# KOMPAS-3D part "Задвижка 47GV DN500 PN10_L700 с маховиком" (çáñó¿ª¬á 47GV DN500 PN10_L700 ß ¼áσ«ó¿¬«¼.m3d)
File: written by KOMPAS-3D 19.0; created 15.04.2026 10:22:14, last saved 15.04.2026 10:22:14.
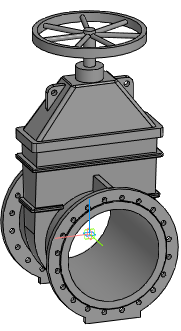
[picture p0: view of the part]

Document properties: Автор: Евгений; Полное имя файла: Z:\3.Личные\kachalov\3d для проектировщиков\2.1 Тип 47GV, 47GV.Z\Задвижка 47GV_DN40-DN600\stp_Задвижка 47GV\Задвижка 47GV DN500 PN10_L700 с маховиком.m3d

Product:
- Part/product: Задвижка 47GV DN500 PN10_L700 с маховиком

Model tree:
1. Операция без истории:1  (labels: Задвижка 47GV DN500 PN10_L700 с маховиком)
